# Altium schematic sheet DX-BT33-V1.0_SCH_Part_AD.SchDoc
size A4; SheetNumber: 1; SheetTotal: 1
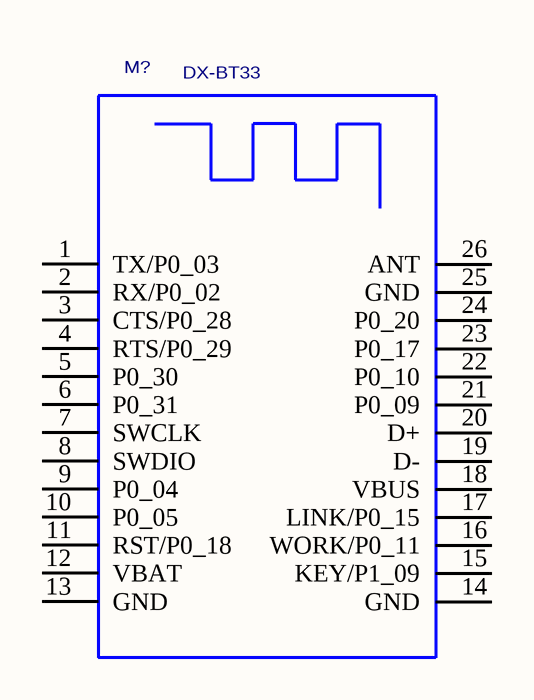
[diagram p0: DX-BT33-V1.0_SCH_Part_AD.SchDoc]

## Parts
M?  DX-BT33

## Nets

Not connected (* = marked no-connect by the designer): M? 1(TX/P0_03) 2(RX/P0_02) 3(CTS/P0_28) 4(RTS/P0_29) 5(P0_30) 6(P0_31) 7(SWCLK) 8(SWDIO) 9(P0_04) 10(P0_05) 11(RST/P0_18) 12(VBAT) 13(GND) 14(GND) 15(KEY/P1_09) 16(WORK/P0_11) 17(LINK/P0_15) 18(VBUS) 19(D-) 20(D+) 21(P0_09) 22(P0_10) 23(P0_17) 24(P0_20) 25(GND) 26(ANT)

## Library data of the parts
M? = DX-BT39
